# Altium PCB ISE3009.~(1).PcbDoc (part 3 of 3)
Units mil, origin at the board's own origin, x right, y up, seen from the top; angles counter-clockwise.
Board outline 2535 x 2952.76 mil, 4 copper layers (Top Layer, L2_P1, L3_P2, Bottom Layer), stack 90 mil thick; 177 components, 107 nets, 497 pads, 221 vias.
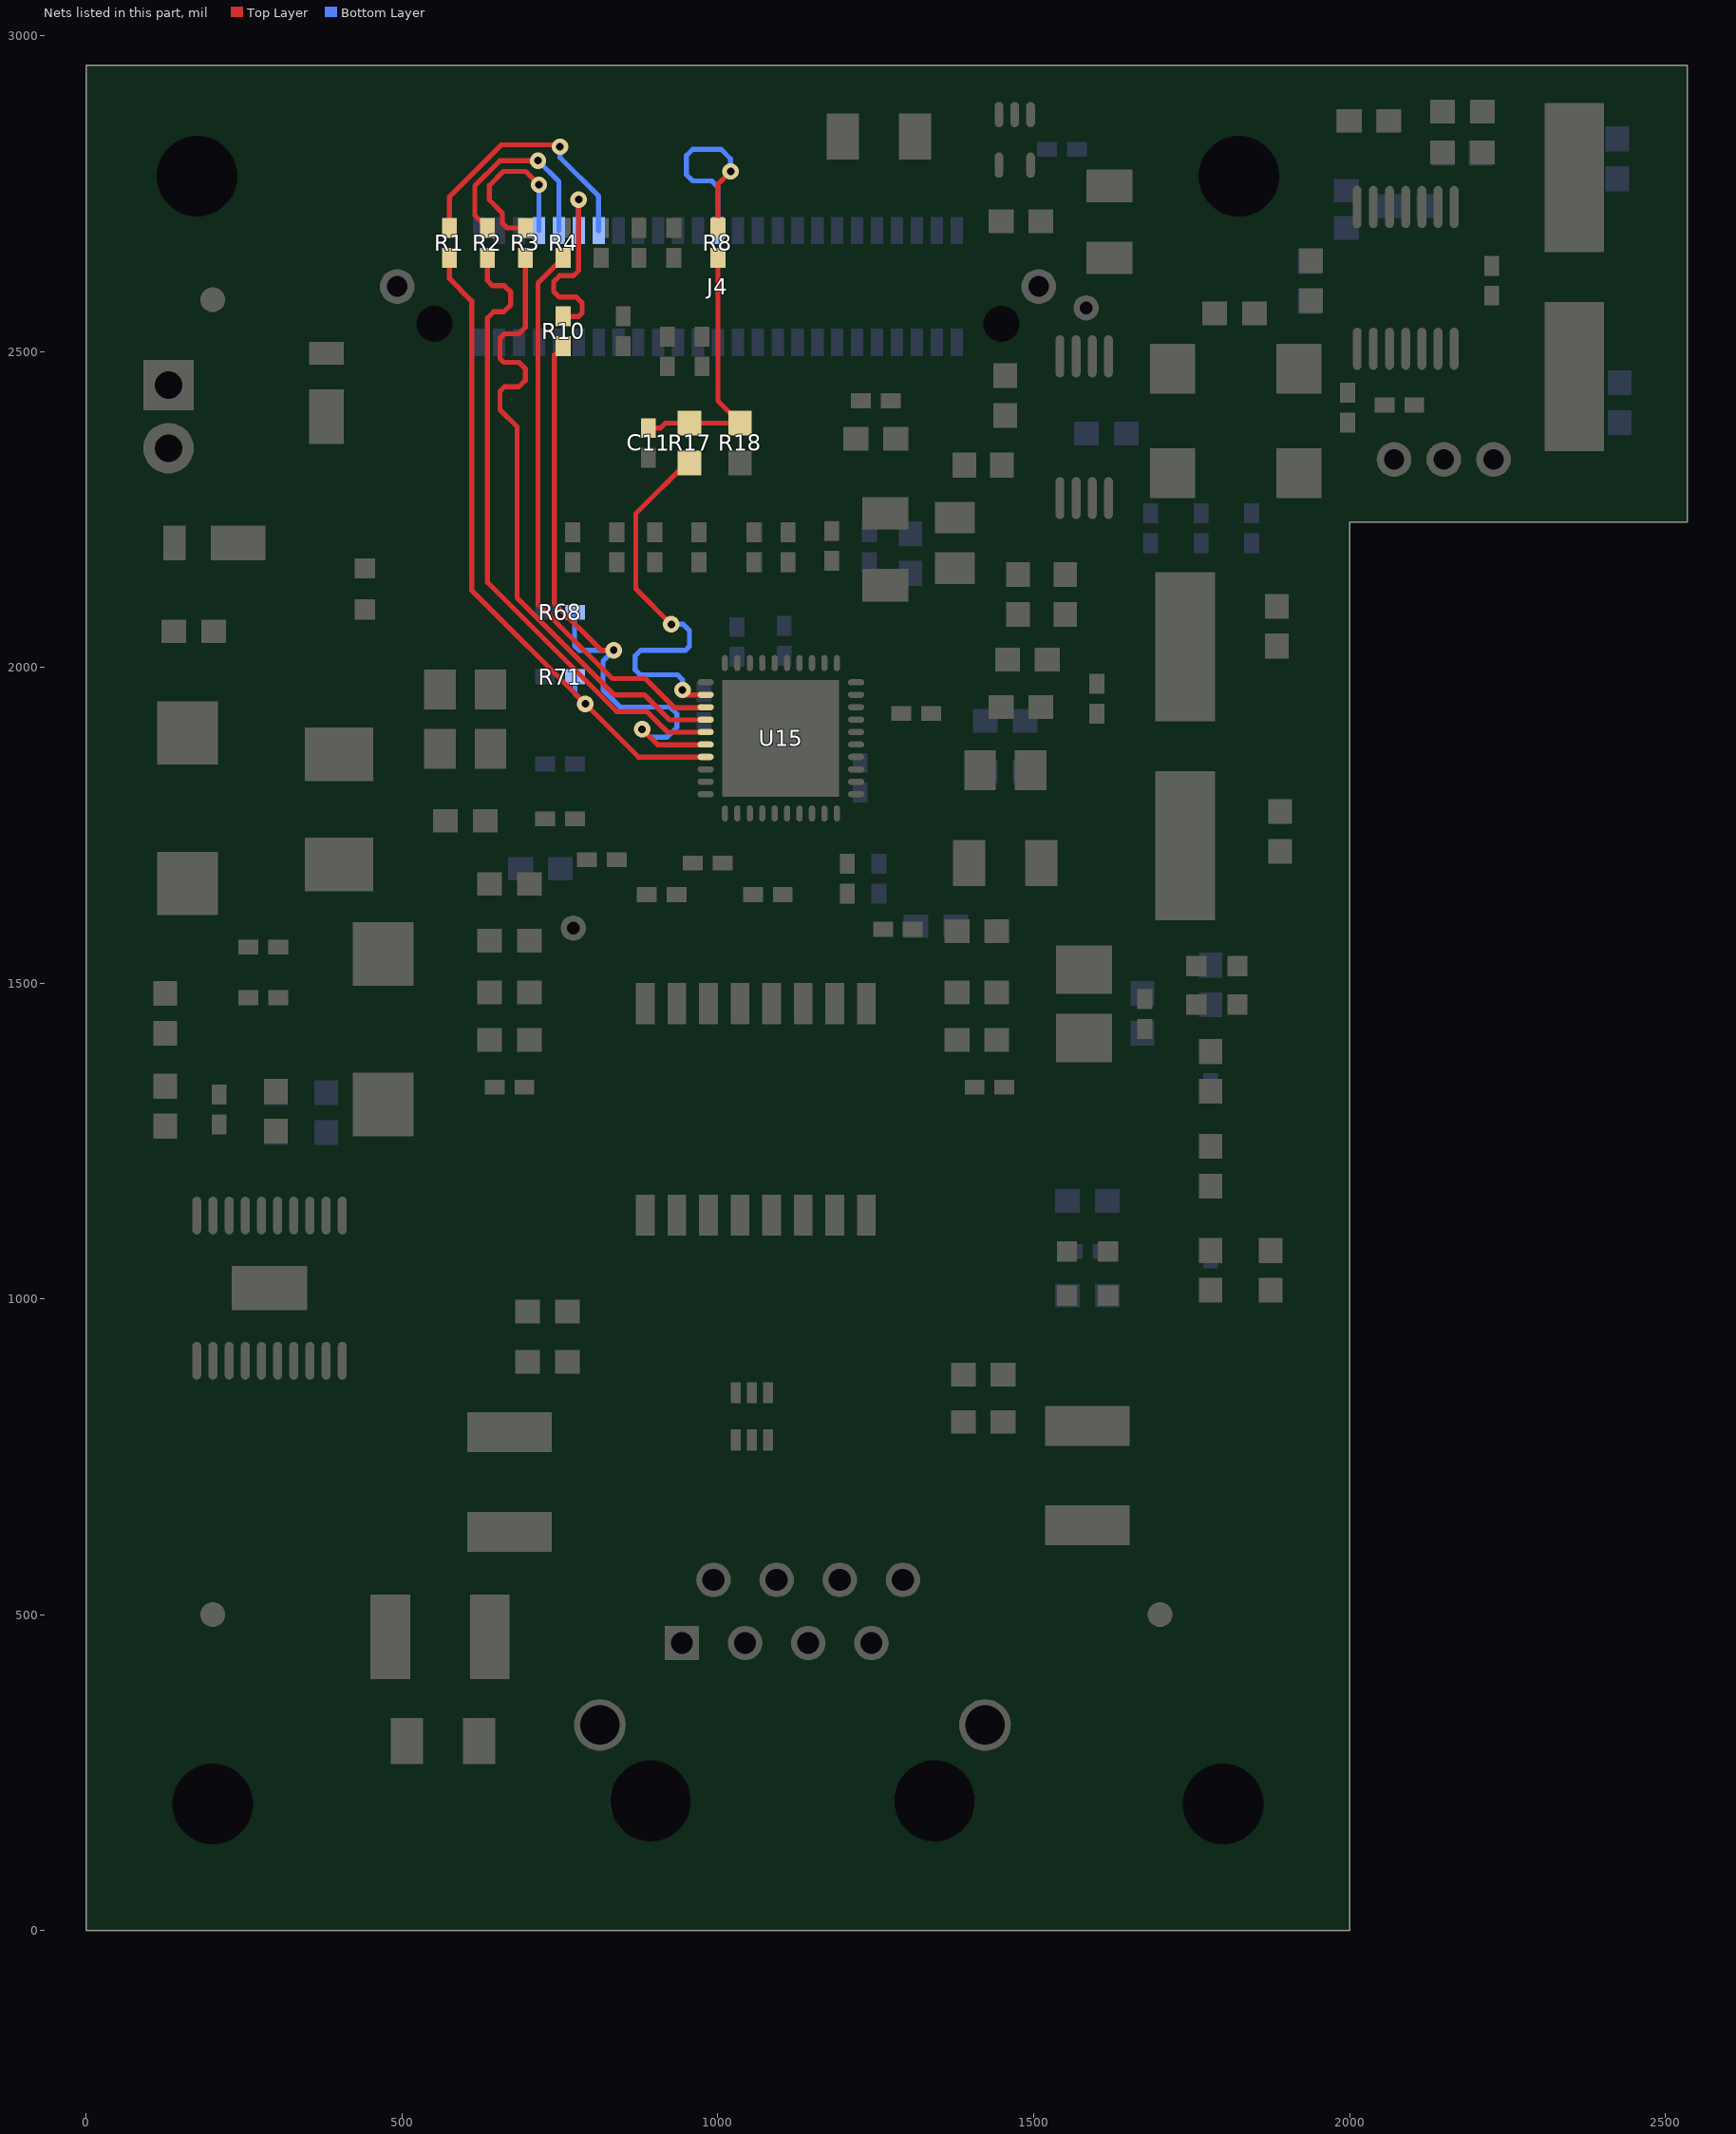
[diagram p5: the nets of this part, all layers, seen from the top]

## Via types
v1: diameter 26, hole 12, Top Layer to Bottom Layer, tented both sides, 104 vias
v2: diameter 32, hole 16, Top Layer to Bottom Layer, tented both sides, 80 vias
v3: diameter 40, hole 20, Top Layer to Bottom Layer, tented both sides, 36 vias
v4: diameter 40, hole 16, Top Layer to Bottom Layer, tented both sides, 1 vias

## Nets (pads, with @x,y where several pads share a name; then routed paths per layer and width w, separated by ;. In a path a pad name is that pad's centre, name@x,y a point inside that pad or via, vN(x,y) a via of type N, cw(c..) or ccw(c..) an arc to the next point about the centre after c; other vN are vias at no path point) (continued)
TX_CLK: R17.1 U15.2 | length 628.5
  Top Layer w8: v1(926,2068) 870,2124 870,2243.28 950.22,2323.5 R17.1@955,2323.5 ; v1(944,1964) 951.94,1956.06 980.59,1956.06 U15.2@982.56,1956.06
  Bottom Layer w8: v1(926,2068) 945,2068 955,2058 955,2033 948.72,2026.72 877.72,2026.72 869,2018 869,1996 877,1988 936,1988 944,1980 v1(944,1964)
TX_CLK_1: C11.1 R8.1 R17.2 R18.1 | length 424.5
  Top Layer w8: C11.1@890,2378.62 909.12,2378.62 917,2386.5 R17.2@955,2386.5 R18.1@1035,2386.5 1000,2421.5 R8.1@1000,2648.23
TX_CLK_2: J4.25 R8.2 | length 355.1
  Top Layer w8: R8.2@1000,2695.47 1000,2765 v1(1020,2785)
  Bottom Layer w8: J4.25@1000.01,2691.34 1000.01,2759.99 990,2770 960,2770 950,2780 950,2810 960,2820 1005,2820 1020,2805 v1(1020,2785)
TX_EN: R4.1 U15.3 | length 900.6
  Top Layer w8: R4.1@755,2648.23 715,2608.23 715,2099.73 832.73,1982 884.85,1982 930.85,1936 982.18,1936 U15.3@982.56,1936.38
TXD0: R3.1 U15.4 | length 1020.8
  Top Layer w8: R3.1@695,2648.23 695,2538 685,2528 662,2528 655,2521 655,2488.85 661,2482.85 685.15,2482.85 695,2473 695,2454 685,2444 662,2444 655,2437 655,2407.85 682,2380.85 682,2110.11 836.11,1956 884,1956 923.31,1916.69 980.59,1916.69 U15.4@982.56,1916.69
TXD1: R2.1 U15.5 | length 1010.7
  Top Layer w8: R2.1@635,2648.23 635,2612 643,2604 662,2604 672,2594 672,2574 660.85,2562.85 645,2562.85 635,2552.85 635,2134.48 839.48,1930 887.37,1930 920.36,1897.01 980.59,1897.01 U15.5@982.56,1897.01
TXD2: R10.1 R68.2 U15.6 | length 1059.2
  Top Layer w8: R10.1@755,2508.23 741,2494.23 741,2100.85 815,2026.85 v1(835,2026.85) ; v1(880,1901.85) 904.53,1877.32 980.59,1877.32 U15.6@982.56,1877.32
  Bottom Layer w8: R68.2@773.62,2086.85 773,2086.23 773,2034 780.15,2026.85 v1(835,2026.85) 818,2009.85 818,1964 845,1937 924,1937 935,1926 935,1905 919,1889 892.85,1889 v1(880,1901.85)
TXD3: R1.1 R71.2 U15.7 | length 1072.8
  Top Layer w8: R1.1@575,2648.23 575,2615 610,2580 610,2121.85 v1(790,1941.85) 874.21,1857.64 980.59,1857.64 U15.7@982.56,1857.64
  Bottom Layer w8: R71.2@773.62,1985 773.62,1958.23 v1(790,1941.85)
TXD_0: J4.7 R3.2 | length 276.9
  Top Layer w8: R3.2@695,2695.47 666.19,2695.47 658.81,2702.85 658.81,2719.04 638,2739.85 638,2762.75 660.25,2785 695.54,2785 v1(716.54,2764)
  Bottom Layer w8: J4.7@716.54,2691.34 716.54,2728.5 v1(716.54,2764)
TXD_1: J4.9 R2.2 | length 315.9
  Top Layer w8: R2.2@635,2695.47 615,2715.47 615,2762.37 654.63,2802 v1(715,2802)
  Bottom Layer w8: v1(715,2802) 748.04,2768.96 J4.9@748.04,2691.34
TXD_2: J4.11 R10.2 | length 324.2
  Top Layer w8: R10.2@755,2555.47 779.47,2555.47 785,2561 785,2577 776,2586 749,2586 740,2595 740,2610.48 749.52,2620 771.3,2620 779.53,2628.23 v1(779.53,2740.31)
  Bottom Layer w8: J4.11@779.53,2691.34 v1(779.53,2740.31)
TXD_3: J4.13 R1.2 | length 417.7
  Top Layer w8: R1.2@575,2695.47 575,2745 657,2827 747,2827 v1(750,2824)
  Bottom Layer w8: v1(750,2824) 750,2807 811.03,2745.97 J4.13@811.03,2691.34
pads on no net: D3.5 FID1.1 FID2.1 FID3.1 FID4.1 FID5.1 FID6.1 J3.MH1 J3.MH2 J4.6 J4.8 J4.10 J4.12 J4.14 J4.16 J4.18 J4.20 J4.26 J4.28 J4.30 J4.32 J4.34 J4.36 J4.38 J4.40 J4.42 J4.43 J4.MH1 J4.MH2 J4.MH3 J4.MH4 LBL1.0 MH1.1 MH2.1 MH3.1 MH4.1 T1.4 T1.5 T1.12 T1.13 U1.1 U1.3 U2.9 U4.2 U4.12 U4.13 U4.14 U4.15 U4.16 U4.18 U4.19 U5.5 U5.7 U15.8 U15.9 U15.10
copper on no net: | length 5198
  Top Layer w8: 1830,545 1930,545 ; 1830,645 1930,645 ; 1830,745 1930,745 ; 1830,445 1830,845 1930,845 1930,445 1830,445
  L3_P2 w8: 1830,545 1930,545 ; 1830,645 1930,645 ; 1830,745 1930,745 ; 1830,445 1930,445 1930,845 1830,845 1830,445
  L2_P1 w8: 1830,545 1930,545 ; 1830,645 1930,645 ; 1830,745 1928,745 ; 1830,445 1930,445 1930,845 1830,845 1830,445
  Bottom Layer w8: 1830,545 1930,545 ; 1830,645 1930,645 ; 1830,745 1930,745 ; 1830,445 1930,445 1930,845 1830,845 1830,445

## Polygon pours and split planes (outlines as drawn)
GND on Top Layer "Top Layer-No Net" (hatched 90Degree grid 5 track 8, remove dead copper, pour order 43): 425,2109 454,2109 459,2104 459,2079 453,2073 428,2073 410,2055 410,1825 80,1825 69.45,1835.55 69.45,1994.45 90,2015 331,2015
GND on Top Layer "Top Layer-No Net" (hatched 90Degree grid 5 track 8, remove dead copper, pour order 49): 1525,1375 1500,1350 1500,1250 1495,1245 1450,1245 1445,1250 1445,1510 1455,1520 1480,1520 1495,1505 1495,1465 1520,1440 1633,1440 1642,1431 1642,1384 1633,1375
GND on Top Layer "Top Layer-No Net" (hatched 90Degree grid 5 track 8, remove dead copper, pour order 48): 443,1505 435,1512.85 435,1562.85 445,1572.85 491.61,1572.85 495,1577.85 495,1780 515,1800 565,1800 585,1780 585,1610 605,1590 650,1590 660,1580 660,1545 645,1530 565,1530 540,1505
NetR47_1 on Top Layer "Top Layer-No Net" (hatched 90Degree grid 5 track 8, remove dead copper, pour order 31): 255,1170 205,1170 185,1190 65,1190 50,1205 50,1270 65,1285 225,1285 235,1275 235,1215 260,1190 260,1175
3_3V_PS_E on Top Layer "Top Layer-No Net" (hatched 90Degree grid 5 track 8, remove dead copper, pour order 33): 230,1435 235,1430 235,1375 230,1370 185,1370 175,1360 175,1330 165,1320 75,1320 65,1330 65,1425 75,1435
5V_PS on Top Layer "Top Layer-No Net" (hatched 90Degree grid 5 track 8, remove dead copper, pour order 40): 310,2105 215,2105 205,2115 205,2275 335,2405 415,2405 420,2400 420,2300 405,2285 345,2285 320,2260 320,2115
GND on Top Layer "Top Layer-No Net" (hatched 90Degree grid 5 track 8, remove dead copper, pour order 46): 90,865 95,860 120,860 125,865 125,945 135,955 440,955 450,945 450,865 455,860 485,860 490,865 490,1155 485,1160 455,1160 450,1155 450,1075 445,1070 145,1070 130,1085 130,1160 125,1165 95,1165 90,1160
5V_PS on Top Layer "Top Layer-No Net" (hatched 90Degree grid 5 track 8, remove dead copper, pour order 27): 353.98,1171.85 330,1171.85 330,1240 320,1250 270,1250 260,1260 260,1276.85 270,1286.85 360,1286.85 370,1296.85 370,1345 395,1370 575,1370 590,1355 590,1231.85 575,1216.85 378,1216.85 353.98,1192.83
NetD1_2 on Top Layer "Top Layer-No Net" (hatched 90Degree grid 5 track 8, remove dead copper, pour order 39): 320,2480 330,2470 435,2470 450,2455 450,2390 460,2380 565,2380 575,2390 575,2480 565,2490 500,2490 485,2505 485,2540 475,2550 330,2550 320,2540
GND on Top Layer "Top Layer-No Net" (hatched 90Degree grid 5 track 8, remove dead copper, pour order 35): 315,1310 285,1310 285,1415 305,1435 305,1545 315,1555 380,1555 410,1585 498,1585 513,1570 513,1515 503,1505 390,1505 370,1485 370,1440 315,1385
3_3V_PS on Top Layer "Top Layer-No Net" (hatched 90Degree grid 5 track 8, remove dead copper, pour order 34): 265,1485 255,1475 75,1475 65,1485 65,1675 85,1695 250,1695 275,1720 440,1720 440,1650 350,1650 350,1620 330,1600 270,1600 265,1595
GND on Top Layer "Top Layer-No Net" (hatched 90Degree grid 5 track 8, remove dead copper, pour order 30): 500,235 425,235 360,300 360,530 395,565 495,565 510,550 510,245
NetC39_1 on Top Layer "Top Layer-No Net" (hatched 90Degree grid 5 track 8, remove dead copper, pour order 32): 620,770 610,780 610,825 630,845 630,985 660,1015 710,1015 720,1005 720,835 730,825 730,775 725,770
NetC38_1 on Top Layer "Top Layer-No Net" (hatched 90Degree grid 5 track 8, remove dead copper, pour order 37): 1440,785 1450,775 1690,775 1705,790 1705,885 1695,895 1440,895
EARTH on Top Layer "Top Layer-No Net" (hatched 90Degree grid 5 track 8, remove dead copper, pour order 45): 615,70 635,50 1085,55 1575,55 1600,80 1600,570 1625,595 1665,595 1675,605 1675,645 1665,655 1510,655 1495,640 1495,380 1485,370 1395,370 1365,340 705,340 680,365 680,555 730,605 730,635 725,640 610,640 600,630 600,310 615,295
GND on Bottom Layer "Top Layer-No Net" (hatched 90Degree grid 5 track 8, remove dead copper, pour order 52): 1875,1005 1860,1020 1860,1285 1825,1320 1825,1550 1800,1575 1670,1575 1645,1600 1645,1675 1530,1790 1530,1950 1455,2025 1455,2140 1465,2150 1935,2150 1945,2140 1945,1010 1940,1005
GND on Bottom Layer "Top Layer-No Net" (hatched 90Degree grid 5 track 8, remove dead copper, pour order 51): 490,1157.37 490,242.85 483,235 355,235 335,255 335,595 315,615 110,615 90,635 90,1195 75,1210 75,1435 90,1450 265,1450 280,1465.54 295,1480.45 303.62,1489.02 303.62,1556.85 366,1556.85 390,1532.99 395,1528.02 395,1440.69 330,1376.07 315,1361.16 315,1321.4 305,1311.46 250,1311.46 235,1296.55 231,1292.57 231,1197.19 254.2,1174.12 473.15,1174.12 485,1162.34
1.8V on Bottom Layer "Top Layer-No Net" (hatched 90Degree grid 5 track 8, remove dead copper, pour order 28): 1560,2880 1560,2790 1570,2780 1650,2780 1670,2800 1670,2880 1650,2900 1580,2900
NetD1_2 on Bottom Layer "Top Layer-No Net" (hatched 90Degree grid 5 track 8, remove dead copper, pour order 36): 310,2450 320,2440 430,2440 510,2360 620,2360 655,2395 655,2740 645,2750 485,2750 310,2575
3_3V_PS on Bottom Layer "Top Layer-No Net" (hatched 90Degree grid 5 track 8, remove dead copper, pour order 50): 265,1510 255,1500 155,1500 140,1515 140,1685 171.5,1716.5 336.5,1716.5 360,1693 360,1610 345,1595 275,1595 265,1585
5V_PS on Bottom Layer "Top Layer-No Net" (hatched 90Degree grid 5 track 8, remove dead copper, pour order 41): 445,1200 435,1210 433,1680 295,1817.85 295,1902.85 230,1967.85 230,2335 272.85,2377.85 365.15,2377.85 415,2328 415,2060 610,1865 610.02,1215.02 595,1200
EARTH on Bottom Layer "Top Layer-No Net" (hatched 90Degree grid 5 track 8, remove dead copper, pour order 44): 618.49,73.49 638.49,53.49 1088.49,58.49 1578.49,58.49 1610,95 1610,642.85 1593.49,658.49 1513.49,658.49 1498.49,643.49 1498.49,383.49 1488.49,373.49 1398.49,373.49 1368.49,343.49 708.49,343.49 683.49,368.49 680,440 680,515 675,520 610,520 605,515 603.49,313.49 618.49,298.49
GND on Bottom Layer "Bottom Layer-No Net" (solid, pour order 29): 1176,1972 1184,1964 1184,1811 1176,1803 1023,1803 1015,1811 1015,1964 1023,1972
3_3V_PS on L3_P2 "Top Layer-No Net" (solid, remove dead copper, pour order 47): 465,810 520,865 520,1090 760.03,1330.03 760,1380 780,1400 1332.82,1400 1360,1372.82 1360,1105 1545,920 1895,920 1930,955 1930,2258 1990,2318 2482,2318 2482,2903 1363,2903 1355,2895 1355,2715 1310,2670 1240,2670 1235,2675 1235,2785 1220,2800 730,2785 710,2785 675,2750 655,2750 590,2685 590,2377.85 536,2324 536,2101 245,1810 245,1590 285,1550 285,1305 255,1275 105,1275 75,1245 75,830 95,810
3_3V_PS_E on L3_P2 "Top Layer-No Net" (hatched 90Degree grid 5 track 8, remove dead copper, pour order 42): 240,1320 80,1320 70,1330 70,2165 200,2295 200,2635 336,2771 336,2838 400,2902 1325,2902 1325,2715 1315,2705 1255,2705 1245,2715 1245,2795 1215,2825 675,2825 550,2700 550,2440 505,2395 505,2115 210,1820 210,1575 255,1530 255,1335
GND on L2_P1 "Top Layer-No Net" (solid, remove dead copper, pour order 38): 510,850 510,1080 805,1375 1320,1375 1335,1360 1335,1125 1550,910 1895,910 1930,945 1930,2250 1990,2310 2490,2310 2490,2911 66,2911 40,2885 40,435 65,410 275,410 370,315 435,315 440,320 440,780

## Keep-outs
Top Layer:
  circle w10: c1825,2777.76 r120
  lines w6: 1423.16,2574.38 cw(c1448.82,2543.7) 1488.82,2543.7 ; 1423.16,2574.38 ccw(c1448.82,2543.7) 1488.82,2543.7 ; 1423.16,2574.38 cw(c1448.82,2543.7) 1488.82,2543.7 ; 525.52,2574.38 ccw(c551.19,2543.7) 591.19,2543.7 ccw(c551.19,2543.7) 525.52,2574.38
Bottom Layer:
  circle w10: c1825,2777.76 r120
  lines w6: 525.52,2574.38 cw(c551.19,2543.7) 591.19,2543.7 cw(c551.19,2543.7) 525.52,2574.38 ; 1423.16,2574.38 ccw(c1448.82,2543.7) 1488.82,2543.7 ccw(c1448.82,2543.7) 1423.16,2574.38
Keep-Out Layer:
  circle w6: c1825,2777.76 r72
  circle w6: c175,2777.76 r72
  circle w6: c175,2777.76 r72
  circle w6: c1825,2777.76 r72
  circle w4: c1448.82,2543.7 r22
  circle w4: c551.19,2543.7 r22
  lines w6: 525.52,2574.38 cw(c551.19,2543.7) 591.19,2543.7 ; 525.52,2574.38 ccw(c551.19,2543.7) 591.19,2543.7 ; 525.52,2574.38 ccw(c551.19,2543.7) 591.19,2543.7 ; 525.52,2574.38 cw(c551.19,2543.7) 591.19,2543.7 ; 1423.16,2574.38 cw(c1448.82,2543.7) 1488.82,2543.7 ; 1423.16,2574.38 ccw(c1448.82,2543.7) 1488.82,2543.7 ; 1423.16,2574.38 cw(c1448.82,2543.7) 1488.82,2543.7 ; 1423.16,2574.38 ccw(c1448.82,2543.7) 1488.82,2543.7 ; 40,40 40,2948 1960,2948 2529,2948 2529,2279 2034,2279 1960,2205 1960,40 40,40
  text ".Layer_Name" at 577,-661.64 h60

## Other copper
Top Layer:
  text "1" at 1905,485 h50 r90
  text ".Layer_Name" at 577,-661.64 h60
L3_P2:
  pour cut-out: 1442.91,1256.57 1412.91,1286.57 1407.91,1286.57 1422.91,1301.57 1442.91,1301.57 1462.91,1281.57 1462.91,1271.57 1447.91,1256.57
  pour cut-out: 1540,1580 1510,1610 1505,1610 1520,1625 1540,1625 1560,1605 1560,1595 1545,1580
  pour cut-out: 510,2370 510,2515 550,2515 575,2490 575,2425 520,2370
  pour cut-out: 1008,1980 1008,1837.85 1155,1837.85 1155,1980
  pour cut-out: 1290,1525 1317.5,1497.5 1330,1510 1335,1510 1310,1535 1300,1535
  pour cut-out: 562.15,1350 508,1295.85 508,1210 552,1166 716,1166 792,1242 792,1342 784,1350
  pour cut-out: 2060.25,2367.48 2244.48,2367.48 2256,2355.96 2256,2312 2244,2300 2058,2300 2043,2315 2043,2351
  pour cut-out: 2465,2342 2485,2362 2485,2316 2466,2316 2465,2317
  text "3" at 1907,679 h50 r90
  text ".Layer_Name" at 600,-661 h60
L2_P1:
  pour cut-out: 163,2690 41,2690 41,2852 163,2852
  pour cut-out: 530,2515 530,2400 565,2400 570,2395 570,2510 565,2515
  pour cut-out: 480,2580 530,2530 540,2530 560,2550 560,2575 525,2610 499.38,2610 485,2595.62 485,2580
  pour cut-out: 30,2390 110,2390 120,2380 120,2310 115,2305 30,2305
  pour cut-out: 2217.69,2367.48 2131.89,2367.48 2104,2339.6 2104,2316 2092,2304 2096,2300 2244,2300 2256,2312 2256,2352 2245,2363 2244,2362 2230,2362 2230,2367
  text "2" at 1903,580 h50 r90
  text ".Layer_Name" at 615,-660 h60
Bottom Layer:
  text "4" at 1906,812 h50 r90
  text ".Layer_Name" at 577,-661.64 h60

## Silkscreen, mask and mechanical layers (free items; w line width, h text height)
Top Overlay:
  circle w8: c332,635 r90
  circle w20: c2196,2757 r6
  circle w10: c1508.28,2267 r12.72
  circle w10: c1112.35,867 r12
  circle w30: c1616,2035 r8
  lines w6: 322,2774 687,2774 ; 547,2768 553,2762 539,2762 545,2768 545,2754 567,2732 ; 659.98,1784.05 686.93,1811 ; 670,2726 545,2726 545,2615 1040,2615 1040,2720 ; 746,2417 877,2417 ; 778,2292 825.5,2292 879.5,2238 ; 796,2110 823,2137 ; 800,2735 910,2735 ; 955,2735 1015,2735 ; 990,2560 1042.99,2560 ; 1020.5,2719.85 1020.65,2720 ; 1057,2134 1057,2117 1066,2108 ; 1121,2294 1168,2247 ; 1131,2441 1186.45,2385.55 ; 1131.5,2142 1136,2142 1152,2126 ; 1170,2327 1209,2288 ; 1310,1479 1310,1511 1341,1542 ; 1356,1191 1356,1306 ; 1392,2383 1423,2352 ; 1403,2506 1411.72,2506 1427.73,2489.98 ; 1460,2642 1531,2642 1558,2615 1558,2594 1565,2587 1565,2586 ; 1965,2482 1974,2482 1979,2487 1979,2497 ; 2005,2779 2110.22,2779 2119.02,2787.8 ; 877,2417 868,2426 868,2408 877,2417 ; 1043.01,2559.98 1042.97,2559.98 1034.99,2552.01 1034.99,2568 1043.01,2559.98 ; 140,856.85 440,856.85 440,1176.85 140,1176.85 140,856.85 ; 1405,2760 1535,2760 1535,2910 1405,2910 1405,2760
  lines w8: 271,699 395,575 ; 606,1135 606,1272.85 ; 606,1272.85 594,1260.85 618,1260.85 606,1272.85 ; 1344,1294 1368,1294 1356,1306 1344,1294
  text "ISE3009" at 75,745 h125
  text "8" at 1279,632 h40
  text "2" at 992,630 h40
  text "Pb" at 272,600 h120
  text "7" at 1446,440 h40
  text ".Layer_Name" at 589,-658 h60
Bottom Overlay:
  lines w6: 840,2243 840,2291 846,2297 ; 895,2244 895,2291 ; 966,2296 976,2286 976,2244 ; 1171,2246 1171,2283 ; 1172,1762 1197,1737 ; 1262,2247 1262,2344 ; 1326,1953 1326,1994 ; 1527,1838 1580,1838 ; 2022.68,2693.5 2030.19,2686 2056,2686 2079,2663 2079,2656 ; 14252,8159 cw(c14252,8121) 14290,8121
  text "1" at 633,2735 h40
  text "49" at 1467,2732 h40
  text "50" at 1444,2431 h40
  text "2" at 626,2429 h40
  text ".Layer_Name" at 577,-661.64 h60
Top Paste:
  text ".Layer_Name" at 577,-661.64 h60
Bottom Paste:
  text ".Layer_Name" at 577,-661.64 h60
Top Solder:
  text "Top Solder Mask" at 577,-661.64 h60
  text ".Layer_Name" at 577,-661.64 h60
Bottom Solder:
  text "Bottom Solder Mask" at 577,-661.64 h60
Drill Guide:
  text ".Layer_Name" at 577,-661.64 h60
M1 Board Outline:
  the board outline again, w10
  text ".Layer_Name" at 577,-661.64 h60
M2 Board Dimensions:
  rectangle: 2878,338 3003,463
  rectangle: 3003,213 3378,338
  lines w7: 2878,338 3878,338 ; 3003,213 3003,463 ; 3128,213 3128,463 ; 3378,213 3378,463 ; 3628,213 3628,463 ; 2878,213 3878,213 3878,463 2878,463 2878,213
  lines w10: 2878,148 2878,168 ; 2938,138 2878,158 ; 2938,178 2878,158 ; 3102.08,158 2878,158 ; 3653.92,158 3878,158 ; 3818,138 3878,158 ; 3818,178 3878,158 ; 3878,148 3878,168
  text "1000 (mil)" at 3112.08,122.01 h60
M3 3D STEP Top:
  text ".Layer_Name" at 577,-661.64 h60
M4 3D STEP Bottom:
  text ".Layer_Name" at 577,-661.64 h60
M5 Assembly Top:
  circle w6: c134,2537 r15.62
  lines w6: 2.05,2494 2.05,2296.85 257.95,2296.85 257.95,2496.85 2.05,2496.85 ; 74.88,2296.85 74.88,2496.85 ; 185.12,2296.85 185.12,2496.85 ; 424.9,2113.08 424.9,2134.25 ; 456.4,2113.08 456.4,2135.92 ; 476.5,2099.5 526.5,2099.5 ; 500.5,2099.5 500.5,2121.65 ; 501.5,2047.5 501.5,2072.5 ; 1388.5,2299.17 1451.5,2299.17 ; 1388.5,2354.54 1451.5,2354.54 ; 1573.58,989.25 1596.42,989.25 ; 1573.58,1020.75 1596.42,1020.75 ; 1573.58,1059.25 1596.42,1059.25 ; 1573.58,1090.75 1596.42,1090.75 ; 1647,1005 1672,1005 ; 1647,1076 1672,1076 ; 1696,1004 1696,1006 ; 1696,1075 1696,1077 ; 1697,980 1697,1030 ; 1697,1005 1722,1005 ; 1697,1051 1697,1101 ; 1697,1076 1722,1076 ; 1778.58,1511.1 1801.42,1511.1 ; 1778.58,1542.6 1801.42,1542.6 ; 1779.16,1450 1802,1450 ; 1779.17,1481.5 1802.01,1481.5 ; 1846.75,1461.75 1871.75,1461.75 ; 1846.79,1526.89 1871.79,1526.89 ; 1895.75,1460.75 1895.75,1462.75 ; 1896.75,1436.75 1896.75,1486.75 ; 1896.75,1461.75 1921.75,1461.75 ; 1896.79,1501.89 1896.79,1551.89 ; 1921.79,1526.89 1896.79,1526.89 ; 2150.5,2786.28 2213.5,2786.28 ; 2150.5,2843.19 2213.5,2843.19 ; 1696,1006 1672,982 1672,1030 1696,1006 ; 1696,1077 1672,1053 1672,1101 1696,1077 ; 1871.79,1501.89 1896.79,1526.89 ; 1871.79,1501.89 1896.79,1526.89 ; 1871.79,1501.89 1871.79,1551.89 1896.79,1526.89 ; 1895.75,1462.75 1871.75,1486.75 1871.75,1438.75 1895.75,1462.75 ; 475.5,2074.5 498.5,2097.5 502.5,2097.5 525.5,2074.5 475.5,2074.5
  lines w10: -292,-733.32 6308,-733.32 ; -292,-529.98 6310,-529.98 ; -292,-326.65 -292,-936.65 3713,-936.65 6310,-936.65 6310,-326.65 -291.5,-326.65 -291.5,-936.65 1284,-936.65 ; 0,640 575,640 575,1230 575,1610 505,1610 505,1625 505,2325 438,2325 438,2948 ; 1679,2951 1679,2577 1362,2577 1362,2147 1362,1888 1543,1888 1543,1564 2000,1564 ; 2173,-936.65 2173,-326.65 ; 3440,-529.98 3440,-326.65 ; 4280,-529.98 4280,-326.65 ; 4902,-943.15 4902,-740.32
  text "POWER SUPPLY" at 18,2898 h55
  text "ETHERNET PHY SECTION" at 540,2890 h75
  text "SECTION" at 77,2854 h55
  text "J1" at 105,2381 h36
  text "OSCILLATOR SECTION" at 2512,2311 h55 r90
  text "FB3" at 1373,2308 h36
  text "LD1" at 316,2092 h36
  text "LD2" at 1651,1515 h36
  text "LD3" at 1829,1391 h36
  text "LD4" at 1419,1059 h36
  text "LD5" at 1421,986 h36
  text "8" at 1280,638 h36
  text "2" at 987,636 h36
  text "ISE3009" at 30,480 h60
  text "7" at 1291,434 h36
  text "COMPONENTS MARKED 'DNP' SHOULD NOT BE POPULATED." at 1574,-116 h60
  text ".VariantName" at 2605,-233 h60
  text "ASSEMBLY VARIANT:" at 1581,-237 h60
  text "PCB VIEWED FROM TOP SIDE" at -228.5,-458.82 h60
  text "BOARD #:" at 2248,-458.82 h60
  text "ISE3009" at 2793.5,-458.82 h60
  text "REV:" at 3638,-458.82 h60
  text ".PCB_Rev" at 3929.5,-458.82 h60
  text "SVN REV:" at 4476,-458.82 h60
  text ".VersionControl_RevNumber" at 4982,-458.82 h60
  text "LAYER NAME : ASSEMBLY TOP" at -224,-658 h60
  text ".plot_File_Name" at 479.52,-856 h60
  text "PLOT NAME =" at -228.5,-867.49 h60
  text "GENERATED    :" at 2250,-867.49 h60
  text ".Print_Date" at 3119.5,-867.49 h60
  text ".Print_Time" at 3848.5,-867.49 h60
  text "TEXAS INSTRUMENTS" at 5113,-867.49 h60
M6 Assembly Bottom:
  lines w4: 1972,2773 1972,2776 2018,2776 2018,2674 1972,2674 1972,2774 ; 2129,2791 2229,2791 2229,2837 2127,2837 2127,2791 2130,2791
  lines w10: -292.5,-530.48 6309.5,-530.48 ; -290.5,-733.82 6309.5,-733.82 ; 1115.5,-943.65 1115.5,-740.82 ; 1737.5,-530.48 1737.5,-327.15 ; 2577.5,-530.48 2577.5,-327.15 ; 3844.5,-937.15 3844.5,-327.15 ; 4733.5,-937.15 6309,-937.15 6309,-327.15 -292.5,-327.15 -292.5,-937.15 2304.5,-937.15 6309.5,-937.15 6309.5,-327.15
  text "FB1" at 2215,2799 h32
  text "49" at 1444,2729 h40
  text "1" at 629,2724 h40
  text "FB2" at 2014,2568 h36 r270
  text "50" at 1426,2443 h40
  text "2" at 628,2440 h40
  text "COMPONENTS MARKED 'DNP' SHOULD NOT BE POPULATED." at 6102,-121.15 h60
  text ".VariantName" at 5058,-237.15 h60
  text "ASSEMBLY VARIANT:" at 6097,-237.15 h60
  text ".VersionControl_RevNumber" at 1035.5,-459.32 h60
  text "SVN REV:" at 1541.5,-459.32 h60
  text ".PCB_Rev" at 2088,-459.32 h60
  text "REV:" at 2379.5,-459.32 h60
  text "ISE3009" at 3224,-459.32 h60
  text "BOARD #:" at 3769.5,-459.32 h60
  text "PCB VIEWED FROM BOTTOM SIDE" at 6246,-459.32 h60
  text "LAYER NAME : ASSEMBLY BOTTOM" at 6239,-670.32 h60
  text "TEXAS INSTRUMENTS" at 904.5,-867.99 h60
  text ".Print_Time" at 2169,-867.99 h60
  text ".Print_Date" at 2898,-867.99 h60
  text "GENERATED    :" at 3767.5,-867.99 h60
  text ".plot_File_Name" at 5440.5,-867.99 h60
  text "PLOT NAME =" at 6246,-867.99 h60
M9 Title Sheet:
  drawing of 57 lines, arcs and shapes, not listed
  text "1" at 739.84,8233.35 h70
  text "2" at 3235.5,8233.35 h70
  text "3" at 5724.84,8233.35 h70
  text "4" at 8231.51,8233.35 h70
  text "5" at 10730.5,8233.35 h70
  text "6" at 13235.5,8233.35 h70
  text "A" at -416.5,7090.35 h70
  text "A" at 14383.5,7090.35 h70
  text "B" at -416.5,4710.35 h70
  text "B" at 14383.5,4710.35 h70
  text "C" at -416.5,2335.35 h70
  text "C" at 14383.5,2335.35 h70
  text "PROJECT TITLE:" at 11343.5,474.35 h45
  text ".PRJ_Title" at 11393.5,341.02 h70
  text "DESIGNED FOR:" at 11343.5,173.35 h45
  text ".PRJ_Customer" at 11393.5,33.35 h70
  text "D" at -416.5,-34.65 h70
  text "D" at 14383.5,-34.65 h70
  text "FILE NAME:" at 11343.5,-126.65 h45
  text ".PCB_File_Name_No_Path" at 11393.5,-246.65 h70
  text "Texas Instruments (TI) and/or its licensors do not warrant the accuracy or completeness of this specification" at 6374,-408.49 h45
  text "ENGINEER:" at 11343.5,-416.65 h45
  text "LAYOUT BY:" at 12848.5,-416.65 h45
  text "or any information contained therein. TI and/or its licensors do not warrant that this design will meet" at 6329.01,-521.15 h45
  text "the specifications, will be suitable for your application or fit for any particular purpose, or will operate in" at 6329.01,-633.82 h45
  text "ALTIUM DESIGNER VERSION:" at 12848.5,-726.65 h45
  text "an implementation. TI and/or its licensors do not warrant that the design is production worthy. You should" at 6329.01,-746.48 h45
  text "completely validate and test your design implementation to confirm the system functionality for your application." at 6374,-859.15 h45
  text ".print_Scale" at 11393.5,-859.98 h70
  text ".Application_BuildNumber" at 12899,-859.98 h70
  text "1" at 739.84,-1066.65 h70
  text "2" at 3235.5,-1066.65 h70
  text "3" at 5724.84,-1066.65 h70
  text "4" at 8231.51,-1066.65 h70
  text "5" at 10730.5,-1066.65 h70
  text "6" at 13235.5,-1066.65 h70
M10 Fab Notes:
  drawing of 236 lines, arcs and shapes, not listed
  text "DESIGN INFORMATION" at 12381.02,7006.85 h60
  text "(REFER ALSO ARRAY/PANEL PROFILING INFORMATION)" at 12019.46,6845.14 h60
  text "BOARD SIZE" at 11333.46,6840.85 h60
  text "2952.7MIL" at 11770,6720 h60
  text "X" at 12301.46,6713.03 h60
  text "2535MIL" at 12532.78,6713.03 h60
  text "IMPEDANCE TABLE" at 6959,6683 h60
  text "LAYER" at 7009,6533 h60
  text "REFERENCE LAYER" at 9709,6533 h60
  text "TRACE WIDTH" at 7387,6531 h60
  text "SPACING" at 8191,6527 h60
  text "IMPEDANCE" at 8905,6521 h60
  text "Number of Layers :" at 11736.46,6515.85 h60
  text "4" at 12831.27,6505.85 h60
  text "MIN. TRACK WIDTH:" at 11736.46,6376.85 h60
  text "7" at 12832.7,6376.85 h60
  text "MIL" at 12987.46,6376.85 h60
  text "100 OHM +/-10%" at 8765,6349 h60
  text "7 MIL" at 7558,6348 h60
  text "L2_GND-PLANE" at 9809,6346 h60
  text "TOP" at 7009,6345 h60
  text "16 MIL" at 8247,6340 h60
  text "MIN. CLEARANCE:" at 11736.46,6244.85 h60
  text "MIL" at 12987.46,6244.85 h60
  text "8" at 12827,6238 h60
  text "L3_PWR-PLANE" at 9809,6157 h60
  text "16 MIL" at 8247,6154 h60
  text "BOTTOM" at 6979,6153 h60
  text "7 MIL" at 7556,6151 h60
  text "100 OHM +/-10%" at 8764,6146 h60
  text "MIN. VIA PAD SIZE:" at 11736.46,6112.85 h60
  text "26" at 12802.71,6112.85 h60
  text "MIL" at 12987.46,6112.85 h60
  text "0.177mm (7MIL)" at 12431.46,5971.14 h60
  text "MINIMUM ANNULAR RING" at 11407.23,5966.86 h60
  text "EXTERNAL" at 13139.46,5966.86 h60
  text "PER" at 11607.23,5848.85 h60
  text "IPC-D-275 CLASS 2 LEVEL C" at 11827.23,5848.85 h60
  text "MIL, HOLES" at 13315.46,5736.56 h60
  text "+/-" at 12923,5735.85 h60
  text "+/-" at 13777,5735.85 h60
  text "REGISTRATION TOLERANCES:" at 11407.23,5730.85 h60
  text "METAL" at 12607,5730.85 h60
  text "5" at 13183.2,5730.85 h60
  text "3" at 14016.2,5730.85 h60
  text "MIL" at 14132.46,5730.85 h60
  text "MATERIAL:" at 11332.46,5521.39 h60
  text "FR-4 High Tg" at 12318.9,5381.06 h60
  text "FR-408" at 11753.46,5372.49 h60
  text "OTHER" at 13241.46,5372.49 h60
  text "X" at 11598,5371 h60
  text "63 MIL (1.6mm) +/-10%" at 12073.56,5209.77 h60
  text "THICKNESS:" at 11407.23,5205.49 h60
  text "X" at 11945.4,5205.49 h60
  text "OTHER" at 13358.46,5205.49 h60
  text "TOLERANCE:" at 11407.23,5047.49 h60
  text "X" at 12246.53,5047.49 h60
  text "ANSI IPC-6012 TYPE 3 CLASS 2" at 12433.48,5047.49 h60
  text "OTHER +/-" at 12433.46,4891.49 h60
  text "BOW & TWIST:" at 11407.23,4734.49 h60
  text "X" at 12246.53,4734.49 h60
  text "ANSI IPC-6012 TYPE 3 CLASS 2" at 12433.48,4734.49 h60
  text "OTHER +/-" at 12433.46,4575.98 h60
  text "COPPER THICKNESS (FINISHED):" at 11332.46,4440.49 h60
  text "1.4MIL (1oz)" at 12212.46,4287.77 h60
  text "2MIL (1.4oz)" at 12979.46,4287.77 h60
  text "2.8MIL (2oz)" at 13706.46,4287.77 h60
  text "OUTER:" at 11689.46,4283.49 h60
  text "X" at 12084,4282.85 h60
  text "1.4MIL (1oz)" at 12212.46,4130.77 h60
  text "2.8MIL (2oz)" at 12979.46,4130.77 h60
  text "N/A" at 13706,4131.14 h60
  text "INNER SIGNAL:" at 11400.38,4126.49 h60
  text "X" at 12085.42,4126.49 h60
  text "DRILLING:" at 11332.46,3987.49 h60
  text "REFERENCE:" at 11407.23,3870.49 h60
  text "X" at 12055.46,3870.49 h60
  text "AS SHOWN" at 12242.46,3870.49 h60
  text "X" at 12956.46,3870.49 h60
  text "NC_DRILL FILES" at 13093.46,3870.49 h60
  text "PTH MIN COPPER THICKNESS:" at 11407.23,3712.49 h60
  text "X" at 12757.46,3712.49 h60
  text "1MIL" at 12894.46,3712.49 h60
  text "OTHER" at 13391.46,3712.49 h60
  text "BOARD FINISH:" at 11332.46,3553.49 h60
  text "SILKSCREEN:" at 11487.68,3435.49 h60
  text "X" at 12436.46,3435.49 h60
  text "TOP" at 12562.46,3435.49 h60
  text "X" at 12946.46,3435.49 h60
  text "BOTTOM" at 13073.46,3435.49 h60
  text "SILKSCREEN COLOR:" at 11487.68,3268.49 h60
  text "X" at 12435.42,3268.49 h60
  text "WHITE" at 12562.46,3268.49 h60
  text "OTHER" at 13073.46,3268.49 h60
  text "SOLDER RESIST COLOR:" at 11487.68,3098.49 h60
  text "X" at 12055.42,2939.29 h60
  text "GREEN" at 12182.46,2939.29 h60
  text "BLUE" at 12773.46,2939.29 h60
  text "OTHER" at 13311.46,2939.29 h60
  text "IMMERSION GOLD (ENIG)" at 12393.46,2750.77 h60
  text "ENEPIG" at 13731,2747.49 h60
  text "SURFACE FINISH:" at 11332.46,2746.49 h60
  text "X" at 12206.51,2746.49 h60
  text "IMM. TIN/SILVER OR EQUIV" at 11662,2589.49 h60
  text "OTHER" at 13093.46,2589.49 h60
  text "ARRAY/PANEL:" at 11332.46,2410.49 h60
  text "CUT AND TRIM PER MECH LAYER 1" at 12393.46,2406.2 h60
  text "N.C. ROUTE" at 12393.46,2254.49 h60
  text "X" at 13072.46,2254.49 h60
  text "V. SCORE" at 13259.46,2254.49 h60
  text "CERTIFICATION:" at 11332.46,2117.49 h60
  text "MATERIALS AND WORKMANSHIP FOR ALL PCBS" at 12057.46,2117.49 h60
  text "TO MEET OR EXCEED THE REQUIREMENTS OF:" at 12057.46,2019.49 h60
  text "X" at 11683.96,1882.99 h60
  text "ANSI IPC-A-600F CLASS ->" at 11822.96,1882.99 h60
  text "X" at 13462.02,1882.99 h60
  text "2" at 13580.96,1882.99 h60
  text "1" at 13265.96,1881.49 h60
  text "3" at 13934.96,1881.49 h60
  text "X" at 11686.02,1723.49 h60
  text "UL 94V-0" at 11822.96,1723.49 h60
  text "X" at 12498.02,1723.49 h60
  text "RoHS" at 12634.96,1723.49 h60
  text "OTHER" at 13279.36,1723.49 h60
  text "PER ORDER" at 13676.42,1723.49 h60
  text "ADDITIONAL REQUIREMENTS:" at 11332.46,1582.49 h60
  text "REQUIRED" at 13887.94,1474.56 h60
  text "VIA TENTING:" at 12748.48,1473.56 h60
  text "NONE" at 13466.44,1471.7 h60
  text "X" at 13760.94,1471.7 h60
  text "MICROSECTION:" at 11407.23,1467.49 h60
  text "YES" at 12312.96,1467.49 h60
  text "REQUIRED" at 13174.46,1311.35 h60
  text "BARE BOARD ELEC. TEST:" at 11407.23,1308.49 h60
  text "NONE" at 12712.96,1308.49 h60
  text "X" at 13047.46,1308.49 h60
  text "PER ORDER" at 13766.46,1308.49 h60
  text "MANUFACTURER'S UL:" at 11407.23,1151.49 h60
  text "RAIL" at 12572.96,1147.2 h60
  text "METAL" at 13064.77,1147.2 h60
  text "X" at 13440,1146.85 h60
  text "SILK" at 13576.46,1147.2 h60
M11 Gerber Information:
  lines w10: -292,-733.32 6308,-733.32 ; -292,-529.98 6310,-529.98 ; -292,-326.65 -292,-936.65 3713,-936.65 6310,-936.65 6310,-326.65 -291.5,-326.65 -291.5,-936.65 1284,-936.65 ; 2173,-936.65 2173,-326.65 ; 3440,-529.98 3440,-326.65 ; 4280,-529.98 4280,-326.65 ; 4902,-943.15 4902,-740.32
  text "ALL ARTWORK VIEWED FROM TOP SIDE" at -228.5,-458.82 h60
  text "BOARD #:" at 2248,-458.82 h60
  text "ISE3009" at 2793.5,-458.82 h60
  text "REV:" at 3638,-458.82 h60
  text ".PCB_Rev" at 3929.5,-458.82 h60
  text "SVN REV:" at 4476,-458.82 h60
  text ".VersionControl_RevNumber" at 4982,-458.82 h60
  text "LAYER NAME =" at -228.5,-661.64 h60
  text "PLOT NAME =" at -228.5,-867.49 h60
  text ".plot_File_Name" at 577,-867.49 h60
  text "GENERATED    :" at 2250,-867.49 h60
  text ".Print_Date" at 3119.5,-867.49 h60
  text ".Print_Time" at 3848.5,-867.49 h60
  text "TEXAS INSTRUMENTS" at 5113,-867.49 h60
M12 Stackup:
  lines w6: 11358,7886.5 14216,7886.5 ; 11358,7999.1 14216,7999.1 ; 11298,7171 ccw(c11334,7171) 11334,7135 14240,7135 ccw(c14240,7171) 14276,7171 14276,8097 ccw(c14240,8097) 14240,8133 11334,8133 ccw(c11334,8097) 11298,8097 11298,7171
  text "Layer Stack Up Detail for: ISE3009.PcbDoc" at 11358,8028.25 h51
  text "Layer" at 11358,7957.1 h26
  text "Gerber" at 12358.47,7957.1 h26
  text "Copper" at 13013.18,7957.1 h26
  text "Dielectric" at 13710.35,7957.1 h26
  text "Name" at 11358,7905.1 h26
  text "Document" at 12358.47,7905.1 h26
  text "Thickness" at 13013.18,7905.1 h26
  text "Material" at 13710.35,7905.1 h26
  text "Top Solder Mask" at 11358,7831.52 h36
  text "(.GTS)" at 12358.47,7831.52 h36
  text "Solder Resist" at 13710.35,7831.52 h36
  text "Top Layer" at 11358,7727.56 h36
  text "(.GTL)" at 12358.47,7727.56 h36
  text "1.4mil" at 13013.18,7727.56 h36
  text "FR-4" at 13710.35,7675.58 h36
  text "L2_P1" at 11358,7623.6 h36
  text "(.G1)" at 12358.47,7623.6 h36
  text "1.4mil" at 13013.18,7623.6 h36
  text "FR-4" at 13710.35,7571.63 h36
  text "L3_P2" at 11358,7519.65 h36
  text "(.G2)" at 12358.47,7519.65 h36
  text "1.4mil" at 13013.18,7519.65 h36
  text "FR-4" at 13710.35,7467.67 h36
  text "Bottom Layer" at 11358,7415.69 h36
  text "(.GBL)" at 12358.47,7415.69 h36
  text "1.4mil" at 13013.18,7415.69 h36
  text "Bottom Solder Mask" at 11358,7311.73 h36
  text "(.GBS)" at 12358.47,7311.73 h36
  text "Solder Resist" at 13710.35,7311.73 h36
M13 Component Bodies Top:
  text ".Layer_Name" at 577,-661.64 h60
M14 Component Bodies Bottom:
  text ".Layer_Name" at 577,-661.64 h60
M15 Courtyards Top:
  text ".Layer_Name" at 577,-661.64 h60
M16 Courtyards Bottom:
  text ".Layer_Name" at 577,-661.64 h60
Drill Drawing:
  text ".legend" at 3604.5,882.85 h60
  text "Drill Table" at 3629.5,697.85 h60
  text "DRILL TOLERANCES:" at 3634.73,547.9 h60
  text "FOR PTH : +/-3MILS" at 4692,548 h60
  text "FOR NPTH : +/-2MILS" at 4691,434 h60
  text "FOR 12MIL DRILL VIA : +0/-12MILS" at 4690,312 h60
  text "FOR 16MIL DRILL VIA : +0/-16MILS" at 4690,186 h60
  text ".Layer_Name" at 577,-661.64 h60

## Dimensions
0,0 to 0,2952.76 on M2 Board Dimensions
0,2952.77 to 2535,2952.76 on M2 Board Dimensions
2000,2230 to 2535,2230 on M2 Board Dimensions
2535,2230 to 2535,2952.76 on M2 Board Dimensions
